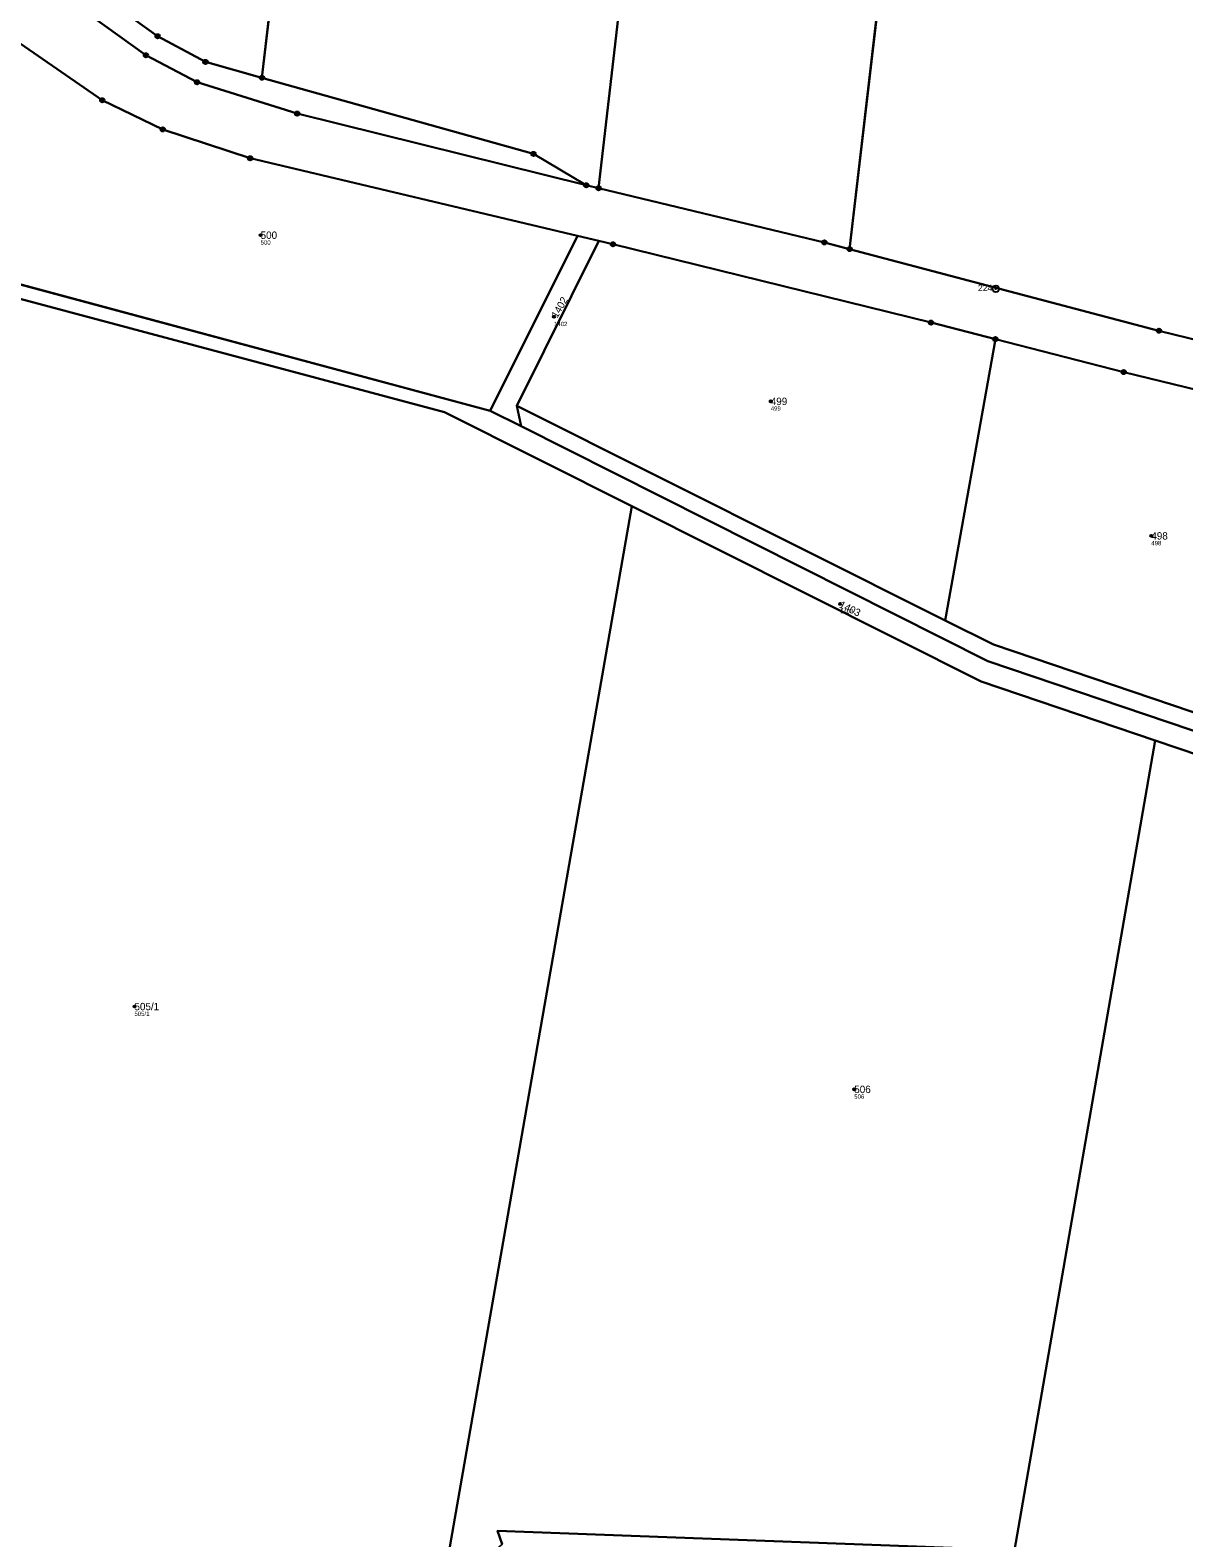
# Model space of a CAD drawing. Extents: x -658203 to -653176, y -1156738 to -1151709.
# Drawn here: x -656136.4 to -655870.9, y -1154387.9 to -1154040.8 of the extents above; entities that cross this region are included whole.
import ezdxf

# ---------------------------------------------------------------- set-up
doc = ezdxf.new("R2010")
doc.units = 0
for name, color, linetype in [('Vrstva 1', 7, 'Continuous'), ('Vrstva 2', 7, 'Continuous'), ('Vrstva 50', 7, 'Continuous'), ('Vrstva 51', 7, 'Continuous'), ('Vrstva 8', 7, 'Continuous')]:
    doc.layers.add(name, color=color, linetype=linetype)

msp = doc.modelspace()

# ---------------------------------------------------------------- linework, layer by layer
at = {"layer": 'Vrstva 1'}
for p, q in [((-656033.21, -1153623.77), (-656083.11, -1154051.75)), ((-656005.62, -1154077.18), (-655954.1, -1153631.31)), ((-655895, -1153636.95), (-655947.85, -1154091.2)), ((-656005.62, -1154077.18), (-656008.44, -1154076.5)), ((-656030.56, -1154128.4), (-656010.49, -1154088.14)), ((-656005.54, -1154089.32), (-656024.44, -1154127.32)), ((-656010.49, -1154088.14), (-656005.54, -1154089.32)), ((-656030.56, -1154128.4), (-656163.37, -1154092.73)), ((-655914.28, -1154111.93), (-655925.87, -1154176.67)), ((-656024.44, -1154127.32), (-655925.87, -1154176.67)), ((-656024.44, -1154127.32), (-656023.4, -1154131.97)), ((-656023.4, -1154131.97), (-656030.56, -1154128.4)), ((-656041.97, -1154402.19), (-655997.96, -1154150.36)), ((-655877.54, -1154204.34), (-655909.91, -1154390.7)), ((-655758.48, -1154244.65), (-655877.54, -1154204.34))]:
    msp.add_line(p, q, dxfattribs=at)
for points in [[(-656008.44, -1154076.5), (-656074.99, -1154060.02), (-656098.03, -1154052.78), (-656109.8, -1154046.58), (-656131.86, -1154030.69), (-656201.38, -1153973.55), (-656224.55, -1153955.87), (-656250.69, -1153936.3), (-656256.1, -1153928.26)], [(-656083.11, -1154051.75), (-656096.09, -1154048.11), (-656107.11, -1154042.19), (-656128.93, -1154026.48), (-656134.65, -1154021.78)], [(-656138.74, -1154043.91), (-656119.86, -1154056.93), (-656105.94, -1154063.66), (-656085.81, -1154070.28), (-656010.49, -1154088.14)], [(-656008.44, -1154076.5), (-656020.59, -1154069.29), (-656083.11, -1154051.75)], [(-655947.85, -1154091.2), (-655953.65, -1154089.67), (-656005.62, -1154077.18)], [(-656005.54, -1154089.32), (-656002.33, -1154090.09), (-655929.1, -1154108.13), (-655914.28, -1154111.93)], [(-656185.4, -1154090.22), (-656041.06, -1154128.73), (-655997.96, -1154150.36)], [(-655866.63, -1154112.5), (-655876.66, -1154110), (-655947.85, -1154091.2)], [(-655914.28, -1154111.93), (-655884.74, -1154119.52), (-655833.35, -1154132.07)], [(-655755.03, -1154240.54), (-655916, -1154186.04), (-656023.4, -1154131.97)], [(-655997.96, -1154150.36), (-655917.6, -1154190.78), (-655877.54, -1154204.34)], [(-655925.87, -1154176.67), (-655914.72, -1154182.25), (-655846.11, -1154205.5)], [(-655909.91, -1154390.7), (-656028.85, -1154386.28), (-656027.78, -1154389.31)]]:
    msp.add_lwpolyline(points, dxfattribs=at)
at = {"layer": 'Vrstva 50'}
for centre in [(-656083.4, -1154088), (-656015.87, -1154106.78), (-655965.99, -1154126.26), (-655878.4, -1154157.22), (-655950.02, -1154172.88), (-656112.44, -1154265.57), (-655946.77, -1154284.64)]:
    msp.add_circle(centre, 0.25, dxfattribs=at)
at = {"layer": 'Vrstva 51'}
for points in [[(-656134.65, -1154021.78), (-656128.93, -1154026.48), (-656107.11, -1154042.19), (-656096.09, -1154048.11), (-656083.11, -1154051.75), (-656033.21, -1153623.77), (-656087.74, -1153618.57)], [(-656083.11, -1154051.75), (-656020.59, -1154069.29), (-656008.44, -1154076.5), (-656005.62, -1154077.18), (-655954.1, -1153631.31), (-656033.21, -1153623.77)], [(-656005.62, -1154077.18), (-655953.65, -1154089.67), (-655947.85, -1154091.2), (-655895, -1153636.95), (-655954.1, -1153631.31)], [(-655895, -1153636.95), (-655947.85, -1154091.2), (-655876.66, -1154110), (-655866.63, -1154112.5), (-655811.61, -1153644.9)], [(-656222.78, -1153953.3), (-656256.1, -1153928.26), (-656250.69, -1153936.3), (-656224.55, -1153955.87), (-656201.38, -1153973.55), (-656131.86, -1154030.69), (-656109.8, -1154046.58), (-656098.03, -1154052.78), (-656074.99, -1154060.02), (-656008.44, -1154076.5), (-656020.59, -1154069.29), (-656083.11, -1154051.75), (-656096.09, -1154048.11), (-656107.11, -1154042.19), (-656128.93, -1154026.48), (-656134.65, -1154021.78), (-656192.34, -1153974.37), (-656198.24, -1153969.52)], [(-656138.74, -1154043.91), (-656163.37, -1154092.73), (-656030.56, -1154128.4), (-656010.49, -1154088.14), (-656085.81, -1154070.28), (-656105.94, -1154063.66), (-656119.86, -1154056.93)], [(-656163.37, -1154092.73), (-656216.44, -1154078.63), (-656277.7, -1154062.5), (-656278.11, -1154065.48), (-656185.4, -1154090.22), (-656041.06, -1154128.73), (-655997.96, -1154150.36), (-655917.6, -1154190.78), (-655877.54, -1154204.34), (-655758.48, -1154244.65), (-655756.63, -1154249.72), (-655755.03, -1154240.54), (-655916, -1154186.04), (-656023.4, -1154131.97), (-656030.56, -1154128.4)], [(-656030.56, -1154128.4), (-656023.4, -1154131.97), (-656024.44, -1154127.32), (-656005.54, -1154089.32), (-656010.49, -1154088.14)], [(-656024.44, -1154127.32), (-655925.87, -1154176.67), (-655914.28, -1154111.93), (-655929.1, -1154108.13), (-656002.33, -1154090.09), (-656005.54, -1154089.32)], [(-656111.64, -1154423.92), (-656072.31, -1154429.55), (-656041.97, -1154402.19), (-655997.96, -1154150.36), (-656041.06, -1154128.73), (-656185.4, -1154090.22), (-656241.8, -1154416.36)], [(-655925.87, -1154176.67), (-655914.72, -1154182.25), (-655846.11, -1154205.5), (-655833.35, -1154132.07), (-655884.74, -1154119.52), (-655914.28, -1154111.93)], [(-656023.4, -1154131.97), (-655916, -1154186.04), (-655755.03, -1154240.54), (-655754.34, -1154236.6), (-655813.96, -1154216.4), (-655846.11, -1154205.5), (-655914.72, -1154182.25), (-655925.87, -1154176.67), (-656024.44, -1154127.32)], [(-655909.91, -1154390.7), (-655877.54, -1154204.34), (-655917.6, -1154190.78), (-655997.96, -1154150.36), (-656041.97, -1154402.19), (-656027.78, -1154389.31), (-656028.85, -1154386.28)], [(-655809.71, -1154390.2), (-655798.99, -1154389.96), (-655786.95, -1154395.2), (-655781.81, -1154394.53), (-655756.63, -1154249.72), (-655758.48, -1154244.65), (-655877.54, -1154204.34), (-655909.91, -1154390.7), (-655900.12, -1154391.06), (-655846.46, -1154401.89)]]:
    msp.add_lwpolyline(points, close=True, dxfattribs=at)
for points in [[(-656282.21, -1153938.68), (-656280.27, -1153939.18), (-656269.33, -1153941.98), (-656264, -1153940.18), (-656257.82, -1153944.02), (-656219.72, -1153975.77), (-656178.32, -1154010.73), (-656138.74, -1154043.91), (-656119.86, -1154056.93), (-656105.94, -1154063.66), (-656085.81, -1154070.28), (-656010.49, -1154088.14), (-656005.54, -1154089.32), (-656002.33, -1154090.09), (-655929.1, -1154108.13), (-655914.28, -1154111.93), (-655884.74, -1154119.52), (-655833.35, -1154132.07)], [(-655866.63, -1154112.5), (-655876.66, -1154110), (-655947.85, -1154091.2), (-655953.65, -1154089.67), (-656005.62, -1154077.18), (-656008.44, -1154076.5), (-656074.99, -1154060.02), (-656098.03, -1154052.78), (-656109.8, -1154046.58), (-656131.86, -1154030.69)], [(-655909.91, -1154390.7), (-656028.85, -1154386.28), (-656027.78, -1154389.31)]]:
    msp.add_lwpolyline(points, dxfattribs=at)
at = {"layer": 'Vrstva 8'}
for centre, radius in [((-656107.11, -1154042.19), 0.5), ((-656107.11, -1154042.19), 0.0303), ((-656109.8, -1154046.58), 0.5), ((-656109.8, -1154046.58), 0.0303), ((-656096.09, -1154048.11), 0.5), ((-656096.09, -1154048.11), 0.0303), ((-656083.11, -1154051.75), 0.5), ((-656098.03, -1154052.78), 0.5), ((-656098.03, -1154052.78), 0.0303), ((-656083.11, -1154051.75), 0.0303), ((-656119.86, -1154056.93), 0.5), ((-656119.86, -1154056.93), 0.0303), ((-656074.99, -1154060.02), 0.5), ((-656074.99, -1154060.02), 0.0303), ((-656105.94, -1154063.66), 0.5), ((-656105.94, -1154063.66), 0.0303), ((-656020.59, -1154069.29), 0.5), ((-656085.81, -1154070.28), 0.5), ((-656085.81, -1154070.28), 0.0303), ((-656020.59, -1154069.29), 0.0303), ((-656008.44, -1154076.5), 0.5), ((-656008.44, -1154076.5), 0.0303), ((-656005.62, -1154077.18), 0.5), ((-656005.62, -1154077.18), 0.0303), ((-656002.33, -1154090.09), 0.5), ((-655953.65, -1154089.67), 0.5), ((-655953.65, -1154089.67), 0.0303), ((-656002.33, -1154090.09), 0.0303), ((-655947.85, -1154091.2), 0.5), ((-655947.85, -1154091.2), 0.0303), ((-655914.21, -1154100.37), 0.75), ((-655914.21, -1154100.37), 0.03), ((-655929.1, -1154108.13), 0.5), ((-655929.1, -1154108.13), 0.0303), ((-655876.66, -1154110), 0.5), ((-655876.66, -1154110), 0.0303), ((-655914.28, -1154111.93), 0.5), ((-655914.28, -1154111.93), 0.0303), ((-655884.74, -1154119.52), 0.5), ((-655884.74, -1154119.52), 0.0303)]:
    msp.add_circle(centre, radius, dxfattribs=at)

# ---------------------------------------------------------------- texts
at = {"layer": 'Vrstva 2'}
for s, p in [('500', (-656083.4, -1154088.85)), ('499', (-655965.99, -1154127.11)), ('498', (-655878.4, -1154158.07)), ('505/1', (-656112.44, -1154266.42)), ('506', (-655946.77, -1154285.49))]:
    msp.add_text(s, height=1.7, dxfattribs=at).set_placement(p)
for s, rotation, p in [('1402', 60, (-656015.13, -1154107.21)), ('1403', 334, (-655950.39, -1154173.64))]:
    msp.add_text(s, height=1.7, rotation=rotation, dxfattribs=at).set_placement(p)
at = {"layer": 'Vrstva 50'}
for s, p in [('500', (-656083.4, -1154090.16)), ('1402', (-656015.87, -1154108.94)), ('499', (-655965.99, -1154128.42)), ('498', (-655878.4, -1154159.38)), ('1403', (-655950.02, -1154175.04)), ('505/1', (-656112.44, -1154267.73)), ('506', (-655946.77, -1154286.8))]:
    msp.add_text(s, height=1, dxfattribs=at).set_placement(p)
at = {"layer": 'Vrstva 8'}
msp.add_text('224', height=1.5, dxfattribs=at).set_placement((-655918.31, -1154100.87))

doc.saveas('drawing.dxf')
